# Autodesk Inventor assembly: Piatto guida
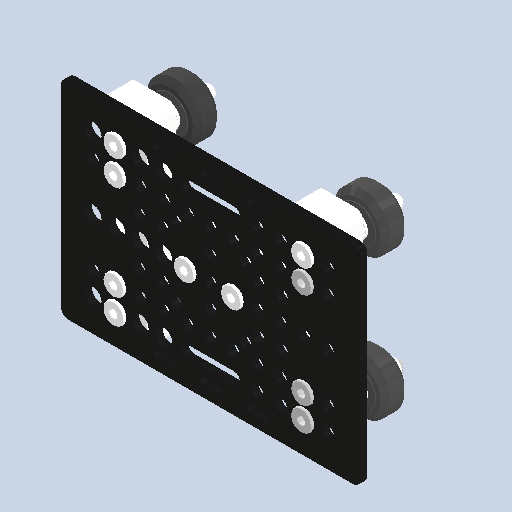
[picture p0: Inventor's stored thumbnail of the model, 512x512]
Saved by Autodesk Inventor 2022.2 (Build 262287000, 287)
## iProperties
Created: 2024-10
Part Number: Piatto guida
Document SubType Name: Assembly
Designer: 18907419
Author: 18907419
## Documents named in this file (45)
- C:\Users\18907419\Desktop\automazione\smistamento\Piatto guida.iam
- C:\Users\18907419\Desktop\automazione\smistamento\Solido32.ipt
- C:\Users\18907419\Desktop\automazione\smistamento\Solido1.ipt
- C:\Users\18907419\Desktop\automazione\smistamento\Solido53.ipt
- C:\Users\18907419\Desktop\automazione\smistamento\Solido52.ipt
- C:\Users\18907419\Desktop\automazione\smistamento\Solido56.ipt
- C:\Users\18907419\Desktop\automazione\smistamento\Solido30.ipt
- C:\Users\18907419\Desktop\automazione\smistamento\Solido29.ipt
- C:\Users\18907419\Desktop\automazione\smistamento\Solido28.ipt
- C:\Users\18907419\Desktop\automazione\smistamento\Solido26.ipt
- C:\Users\18907419\Desktop\automazione\smistamento\Solido25.ipt
- C:\Users\18907419\Desktop\automazione\smistamento\Solido24.ipt
- C:\Users\18907419\Desktop\automazione\smistamento\Solido23.ipt
- C:\Users\18907419\Desktop\automazione\smistamento\Solido22.ipt
- C:\Users\18907419\Desktop\automazione\smistamento\Solido21.ipt
- C:\Users\18907419\Desktop\automazione\smistamento\Solido57.ipt
- C:\Users\18907419\Desktop\automazione\smistamento\Solido19.ipt
- C:\Users\18907419\Desktop\automazione\smistamento\Solido18.ipt
- C:\Users\18907419\Desktop\automazione\smistamento\Solido17.ipt
- C:\Users\18907419\Desktop\automazione\smistamento\Solido16.ipt
- C:\Users\18907419\Desktop\automazione\smistamento\Solido27.ipt
- C:\Users\18907419\Desktop\automazione\smistamento\Solido20.ipt
- C:\Users\18907419\Desktop\automazione\smistamento\Solido59.ipt
- C:\Users\18907419\Desktop\automazione\smistamento\Solido54.ipt
- C:\Users\18907419\Desktop\automazione\smistamento\Solido49.ipt
- C:\Users\18907419\Desktop\automazione\smistamento\Solido48.ipt
- C:\Users\18907419\Desktop\automazione\smistamento\Solido31.ipt
- C:\Users\18907419\Desktop\automazione\smistamento\Solido14.ipt
- C:\Users\18907419\Desktop\automazione\smistamento\Solido13.ipt
- C:\Users\18907419\Desktop\automazione\smistamento\Solido12.ipt
- C:\Users\18907419\Desktop\automazione\smistamento\Solido11.ipt
- C:\Users\18907419\Desktop\automazione\smistamento\Solido15.ipt
- C:\Users\18907419\Desktop\automazione\smistamento\Solido50.ipt
- C:\Users\18907419\Desktop\automazione\smistamento\Solido10.ipt
- C:\Users\18907419\Desktop\automazione\smistamento\Solido9.ipt
- C:\Users\18907419\Desktop\automazione\smistamento\Solido51.ipt
- C:\Users\18907419\Desktop\automazione\smistamento\Solido7.ipt
- C:\Users\18907419\Desktop\automazione\smistamento\Solido5.ipt
- C:\Users\18907419\Desktop\automazione\smistamento\Solido55.ipt
- C:\Users\18907419\Desktop\automazione\smistamento\Solido8.ipt
- C:\Users\18907419\Desktop\automazione\smistamento\Solido4.ipt
- C:\Users\18907419\Desktop\automazione\smistamento\Solido3.ipt
- C:\Users\18907419\Desktop\automazione\smistamento\Solido58.ipt
- C:\Users\18907419\Desktop\automazione\smistamento\Solido6.ipt
- C:\Users\18907419\Desktop\automazione\smistamento\Solido2.ipt
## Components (44 placed, 44 different names)
1. Solido32:1
2. Solido1:1
3. Solido53:1
4. Solido52:1
5. Solido56:1
6. Solido30:1
7. Solido29:1
8. Solido28:1
9. Solido26:1
10. Solido25:1
11. Solido24:1
12. Solido23:1
13. Solido22:1
14. Solido21:1
15. Solido57:1
16. Solido19:1
17. Solido18:1
18. Solido17:1
19. Solido16:1
20. Solido27:1
21. Solido20:1
22. Solido59:1
23. Solido54:1
24. Solido49:1
25. Solido48:1
26. Solido31:1
27. Solido14:1
28. Solido13:1
29. Solido12:1
30. Solido11:1
31. Solido15:1
32. Solido50:1
33. Solido10:1
34. Solido9:1
35. Solido51:1
36. Solido7:1
37. Solido5:1
38. Solido55:1
39. Solido8:1
40. Solido4:1
41. Solido3:1
42. Solido58:1
43. Solido6:1
44. Solido2:1
